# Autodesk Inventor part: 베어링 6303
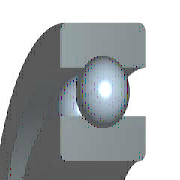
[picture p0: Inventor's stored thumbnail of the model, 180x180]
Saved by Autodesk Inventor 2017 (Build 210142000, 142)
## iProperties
IsCustomPart: 1
Created: 2012-02
Part Number: 베어링 6303
Material: 강철, 연강
Description: 단열 볼 베어링
Document SubType Name: Modeling
Standard: JIS B 1521
Designer: mdu-01
Standards Organization: JIS
Language: ko-KR
Size Designation: SKF 6303
Categories: <MemberInstance><Categories><Category DisplayName="샤프트 부품" InternalName="7f7aeb1f-a693-4053-b835-cee3144e0d98" Mnemonic="SHFT"><Category DisplayName="베어링" Inter
Density: 7.86 g/cm^3
Mass: 109.207 g
Surface Area: 91.3626 cm^2
Volume: 13.894 cm^3
Appearance: 노란색
Author: mdu-01
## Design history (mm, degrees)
node "WorkPoint1"
node "WorkAxis1"
node "WorkPlane3"
node "WorkPlane4"
node "WorkPoint2"
body "Solid1"
node "스케치1"
revolve "회전1" stored, may be unused: angle "d6" = 360 deg
revolve "회전2" stored, may be unused: angle "d10" = 360 deg
node "스케치4"
revolve "회전3" stored, may be unused: angle "d16" = 360 deg
pattern_circular "원형 배열1" dims "d17" = 57.33333 (= msp_pocet), angle "d19" = 360 deg
fillet "모깎기1" dims "d20" = 1 (= r)
sketch "스케치2"
  geometry: L1 (8.5, 14)-(23.5, 14); L2 (8.5, 0)-(8.5, 14); L3 (23.5, 0)-(8.5, 0); L4 (23.5, 14)-(23.5, 0); L5 (0, 0)-(0, 20); L6 (0, 0)-(0, 20); L7 (-7.2, 0)-(43.2, 0) reference
  constraints: 12 end point, 3 vertical, 2 horizontal, 1 collinear, 1 other
  dimensions: "d1" = 17 diameter of L1.start L5 (= Diam); "d3" = 47 diameter of L1.end L5 (= DD); "d5" = 14 distance of L2.start L1.start (= msp_mdtd2)
sketch "스케치3"
  geometry: L1 (18.7, 14)-(18.7, 10.6); L2 (13.3, 14)-(18.7, 14); L3 (13.3, 10.6)-(13.3, 14); L4 (13.3, 0)-(13.3, 3.4); L5 (18.7, 0)-(13.3, 0); L6 (18.7, 3.4)-(18.7, 0); L7 (23.5, 0)-(-23.5, 0) reference; L8 (23.5, 14)-(-23.5, 14) reference; L9 (0, -42.29)-(0, 61.29); L10 (0, 82.007)-(0, -63.007) reference; A1 r 4.5 centre (16, 7) between (18.7, 3.4) and (18.7, 10.6); A2 r 4.5 centre (16, 7) between (13.3, 10.6) and (13.3, 3.4)
  constraints: 14 end point, 4 collinear, 4 point on circle, 4 vertical, 2 centre point, 2 concentric, 2 horizontal, 2 point on line
  dimensions: "d9" = 9 diameter of A1 (= msp_mdtd6); "d21" = 13.3 distance between parallel lines of L9 L4 (= 0.5 x msp_d1); "d22" = 16 distance from line of L9 A1.centre (= 0.5 x msp_ds); "d23" = 18.7 distance between parallel lines of L9 L6 (= 0.5 x msp_dd1)
sketch "스케치5"
  geometry: L1 (16, 2.5)-(16, 11.5); L2 (18.7, 0)-(-18.7, 0) reference; L3 (16, 2.5)-(16, 11.5); A1 r 4.5 centre (16, 7) between (16, 2.5) and (16, 11.5); A2 r 4.5 centre (16, 7) between (18.7, 3.4) and (18.7, 10.6) reference
  constraints: 4 end point, 2 point on circle, 1 centre point, 1 concentric, 1 vertical
  dimensions: "d13" = 0 horizontal distance of A1.centre L1.start; "d15" = 9.0001 diameter of A1 (computed from msp_mdtd6)
other parameters: "Diam" = 17 [user parameter; used in 3 equation terms], "DD" = 47 [user parameter; used in 3 equation terms], "B" = 14 [user parameter; used in 1 equation term], "r" = 1 [user parameter; used in 1 equation term], "msp_ds" = 32 (= 0.5 x Diam + 0.5 x DD) [user parameter; used in 5 equation terms], "msp_d0" = 9 (= -0.3 x Diam + 0.3 x DD) [user parameter; used in 4 equation terms], "msp_d1" = 26.6 (= msp_ds - 0.6 x msp_d0) [user parameter; used in 1 equation term], "msp_dd1" = 37.4 (= msp_ds + 0.6 x msp_d0) [user parameter; used in 1 equation term], "msp_pom" = 48 (= 1.5 x msp_ds) [user parameter; used in 1 equation term], "msp_mdtd2" = 14 (= B) [user parameter; used in 3 equation terms], "msp_mdtd4" = 32 (= msp_ds) [user parameter], "msp_mdtd6" = 9 (= msp_d0) [user parameter; used in 2 equation terms], "msp_mdtd7" = 7 (= 0.5 x msp_mdtd2) [user parameter], "msp_pocet" = 57.33333 (computed from msp_d0, msp_pom) [user parameter; used in 1 equation term], "d2" = 72 (derived), "d4" = 19 (derived), "d7" = 0, "d8" = 15.6 (derived), "d11" = -14 (computed from msp_mdtd2), "d12" = 0 (derived), "d14" = 15.6001 (derived), "d26" = 0, "d27" = 0, "d28" = 0, "d29" = 0, "d30" = 0
